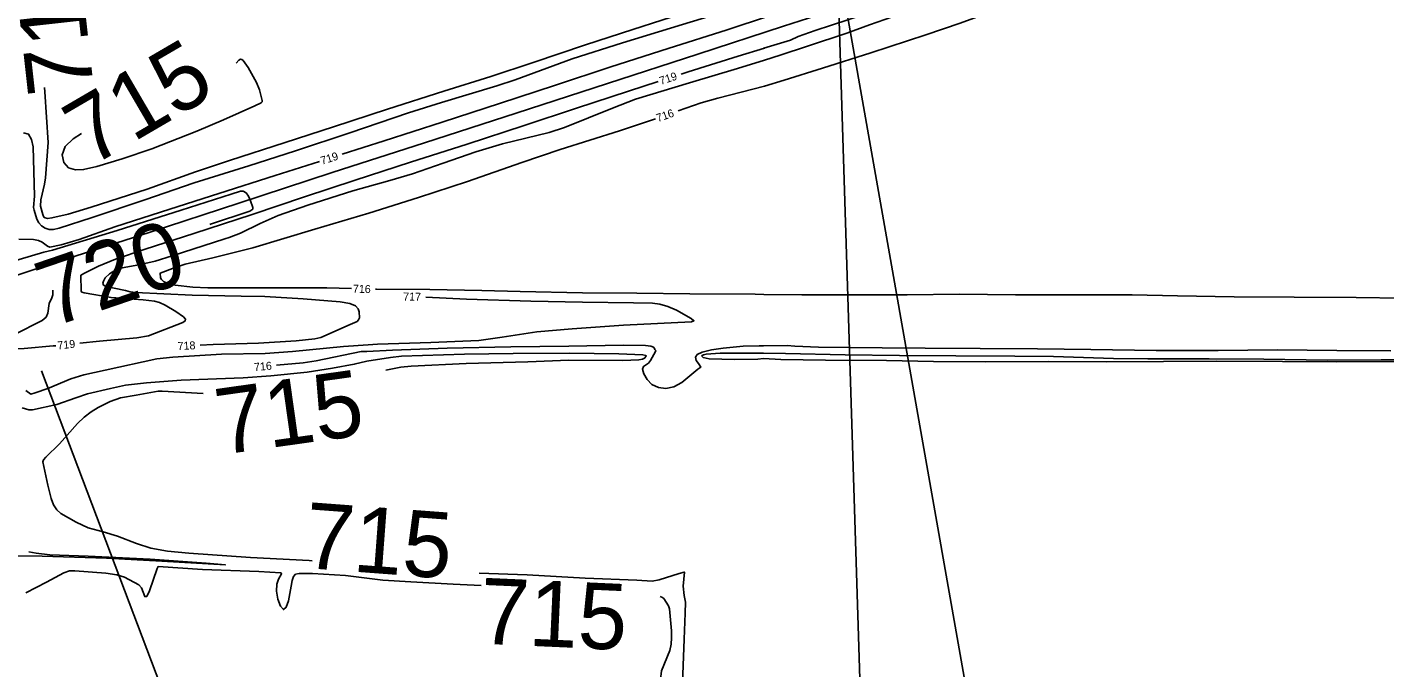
# Model space of a CAD drawing. Extents: x -468563856 to 36492962, y -306094093 to 11899197.
# Drawn here: x 1821764 to 1822443, y 530800 to 531121 of the extents above; entities that cross this region are included whole.
import ezdxf

# ---------------------------------------------------------------- set-up
doc = ezdxf.new("R2010")
doc.units = 0
for name, color, linetype in [('DT_X_Contour_Minor', 7, 'Continuous'), ('Level 14', 7, 'Continuous'), ('Level 19', 7, 'Continuous'), ('Level 40', 7, 'Continuous'), ('SH_Text', 7, 'Continuous')]:
    doc.layers.add(name, color=color, linetype=linetype)

msp = doc.modelspace()

# ---------------------------------------------------------------- linework, layer by layer
at = {"layer": 'DT_X_Contour_Minor'}
for points in [[(1822132.44, 531110.25), (1822145.7, 531114.41), (1822149.59, 531116.1), (1822157.97, 531119.11), (1822182.56, 531127.18), (1822210.23, 531136.13), (1822235.24, 531143.64), (1822260.34, 531151.8), (1822284.89, 531160.12), (1822311.53, 531168.93), (1822338.53, 531177.94), (1822366.96, 531187.21), (1822392.98, 531195.61), (1822415.55, 531202.84), (1822441.7, 531212.02), (1822457.43, 531217.42), (1822485.67, 531226.7), (1822513.96, 531235.56), (1822541.9, 531244.31), (1822572.45, 531253.71), (1822600.65, 531262.79), (1822628.9, 531272.08), (1822654.94, 531280.76), (1822671.39, 531286.17)], [(1822451.09, 531237.66), (1822425.97, 531229.73), (1822397.32, 531220.92), (1822371.29, 531212.64), (1822343.96, 531203.86), (1822312.87, 531193.61), (1822281.22, 531183.05), (1822251.62, 531173.44), (1822228.43, 531166.15), (1822200.9, 531157.19), (1822172.17, 531147.85), (1822146.73, 531139.54), (1822115.83, 531129.58), (1822091.67, 531122.23), (1822061.68, 531112.93), (1822036.58, 531104.94), (1822007.99, 531094.5), (1821998.97, 531091.41), (1821971.29, 531083.21), (1821954.8, 531077.96), (1821925.41, 531068.03), (1821898.18, 531059), (1821874.87, 531051.43), (1821847.61, 531042.99)], [(1822390.37, 531209.96), (1822374.4, 531204.87), (1822346.31, 531195.61), (1822319.96, 531186.97), (1822293.76, 531178.31), (1822267.78, 531169.88), (1822242.79, 531161.78), (1822215.73, 531152.9), (1822188.84, 531144.17), (1822163.48, 531135.96), (1822134.64, 531126.33), (1822114.03, 531119.54), (1822084.57, 531110.22), (1822055.85, 531101), (1822027.7, 531091.72), (1822000.77, 531082.85), (1821971.55, 531073.36), (1821942.62, 531064.04), (1821921.62, 531057.31)], [(1822462.06, 531210.89), (1822430.53, 531201.7), (1822402.62, 531192.71), (1822377.11, 531184.99), (1822350.02, 531176.7), (1822330.87, 531170.59), (1822305.34, 531162.02), (1822292.11, 531157.05), (1822275.26, 531150.3), (1822258.28, 531144.41), (1822244.67, 531140), (1822228.28, 531135.36), (1822209.84, 531130.07), (1822196.74, 531125.99), (1822185.22, 531121.96), (1822173.88, 531117.8), (1822154.26, 531111.38), (1822140.51, 531106.9), (1822132.67, 531104.27)], [(1822132.63, 531091.28), (1822142.54, 531094.32), (1822161.67, 531100.32), (1822185.92, 531108.05), (1822213.28, 531117), (1822230.57, 531122.82), (1822260.92, 531133.96), (1822287.86, 531143.13), (1822308.78, 531150.57), (1822317.45, 531153.55), (1822338.87, 531160.16), (1822364.37, 531167.87), (1822393.59, 531176.61), (1822417.02, 531183.69), (1822450.89, 531193.89)], [(1821772.8, 531090.67), (1821772.9, 531088.48), (1821774.65, 531063.14), (1821773.24, 531045.43), (1821772.74, 531042.31), (1821770.99, 531034.38), (1821770.86, 531031.33), (1821771.95, 531027.18), (1821772.52, 531025.85), (1821773.06, 531025.37), (1821774.22, 531025.17), (1821776.51, 531025.42), (1821784.6, 531027.33), (1821796.12, 531030.76), (1821824.03, 531039.86), (1821848.32, 531048.39), (1821865.31, 531054.13), (1821893.01, 531063.06), (1821917.23, 531070.96), (1821944.16, 531079.74), (1821972.41, 531088.87), (1821995.94, 531096.18), (1822017.08, 531103.1), (1822043.27, 531112.04), (1822066.95, 531119.71), (1822095.94, 531128.96)], [(1822090.98, 531097.33), (1822094.48, 531098.47), (1822119.54, 531106.3), (1822132.69, 531110.33)], [(1821868.51, 531102.86), (1821869.95, 531104.38), (1821870.78, 531104.78), (1821871.42, 531104.73), (1821872.13, 531104.14), (1821874.52, 531100.61), (1821878.8, 531093.11), (1821880.27, 531089.55), (1821881.61, 531084.22), (1821881.56, 531083.54), (1821881.13, 531083), (1821877.94, 531081.52), (1821862.25, 531074.53), (1821848.98, 531068.83), (1821826.36, 531060.01), (1821811.63, 531055.03), (1821798.87, 531051.05), (1821792.32, 531049.62), (1821788.34, 531049.45), (1821784.79, 531050.5), (1821782.38, 531053.21), (1821781.66, 531057.03), (1821783.17, 531061.19), (1821787.05, 531064.97), (1821791.26, 531067.61)], [(1822132.67, 531104.32), (1822119.18, 531100.1), (1822095.25, 531093.03), (1822068.18, 531084.78), (1822056.74, 531080.38), (1822032.78, 531070.72), (1822024.98, 531068.18), (1822001.8, 531062.47), (1821988.45, 531058.48), (1821972.04, 531052.8), (1821956.8, 531047.49), (1821945.4, 531044.1), (1821926.86, 531038.88), (1821904.49, 531031.78), (1821889.59, 531026.56), (1821880.6, 531022.61), (1821870.74, 531017.72), (1821865.08, 531015.63), (1821862.9, 531014.98), (1821836.58, 531006.39), (1821828.13, 531003.7), (1821819.92, 531001.99), (1821811.52, 531000.51), (1821807.91, 530999.12), (1821805.34, 530997.41), (1821803.18, 530995.5), (1821802.22, 530993.73), (1821801.96, 530992.73), (1821802.3, 530991.8), (1821803.53, 530991.12), (1821807.64, 530990.25), (1821813.26, 530989.15), (1821815.62, 530988.43), (1821818.3, 530988.11), (1821846.59, 530986.73), (1821871.08, 530986.33), (1821882.9, 530986.11), (1821902.15, 530984.85), (1821920.56, 530983.38), (1821925.35, 530982.55), (1821928.24, 530981.35), (1821929.58, 530979.89), (1821930.06, 530978.34), (1821930.2, 530975.49), (1821929.81, 530974.4), (1821929.03, 530973.63), (1821925.59, 530972.09), (1821910.96, 530965.6), (1821907.83, 530964.83), (1821898.53, 530963.89), (1821879.69, 530962.76), (1821857.05, 530962.07), (1821850.54, 530961.79)], [(1821790.41, 530962.74), (1821800.32, 530963.8), (1821818.88, 530965.42), (1821824.83, 530966.46), (1821841.91, 530973.04), (1821843.03, 530973.86), (1821843.19, 530974.77), (1821842.33, 530975.85), (1821838.36, 530978.58), (1821833.02, 530981.75), (1821830.3, 530983.01), (1821827.69, 530983.8), (1821822.08, 530984.46), (1821806.05, 530985.57), (1821792.59, 530987.92), (1821791.44, 530988.3), (1821791.08, 530988.82), (1821790.94, 530996.75), (1821793.18, 530998.01), (1821799.84, 531001.22), (1821808.3, 531004.72), (1821823.09, 531009.7), (1821847.51, 531017.65), (1821876.66, 531027.13), (1821902.71, 531035.89), (1821928.08, 531044.26), (1821955.68, 531053.23), (1821984.01, 531062.29), (1822012.57, 531071.62), (1822038.71, 531080.24), (1822064.76, 531088.75), (1822079.58, 531093.6)], [(1822132.63, 531091.28), (1822109.43, 531085.24), (1822101.08, 531082.92), (1822089.48, 531078.91)], [(1822078.13, 531075.01), (1822060.25, 531068.97), (1822030.53, 531059.55), (1822011.44, 531053.19), (1821984.17, 531043.64), (1821959.77, 531035.55), (1821934.88, 531027.85), (1821907.87, 531019.72), (1821876.99, 531010.38), (1821856.89, 531005.5), (1821843.05, 531002.24), (1821838.17, 531000.66), (1821830.54, 530997.71), (1821830.81, 530995.48), (1821831.2, 530994.52), (1821832.24, 530993.52), (1821834.47, 530992.58), (1821838.16, 530991.8), (1821847.01, 530990.78), (1821854.36, 530990.44), (1821883.1, 530990.46), (1821913.84, 530990.35), (1821926.29, 530990.04)], [(1821847.61, 531042.99), (1821822.99, 531034.51), (1821796.53, 531025.61), (1821780.17, 531020.28), (1821777.25, 531019.65), (1821775.03, 531019.65), (1821773.06, 531020.24), (1821771.32, 531021.36), (1821769.91, 531022.93), (1821768.91, 531024.82), (1821767.58, 531029.28), (1821767.29, 531030.68), (1821767.71, 531036.36), (1821767.03, 531060.97), (1821766.33, 531064.71), (1821764.82, 531067.31), (1821762.32, 531067.94)], [(1821910.19, 531053.65), (1821888.05, 531046.57), (1821859.97, 531037.56), (1821835.49, 531029.76), (1821807.9, 531020.91), (1821790.12, 531014.66), (1821781.05, 531011.97), (1821775.39, 531010.76), (1821774.32, 531011.25), (1821771.6, 531013.28), (1821769.81, 531014.05), (1821767.21, 531014.59), (1821759.94, 531014.74)], [(1821855.39, 531022.1), (1821855.71, 531022.2), (1821875.44, 531028.77), (1821876.91, 531029.8), (1821876.89, 531030.58), (1821875.77, 531034), (1821874.79, 531036.26), (1821873.55, 531038.01), (1821872.12, 531038.75), (1821870.69, 531038.73), (1821866.17, 531037.36), (1821841.15, 531029.34), (1821809.03, 531019.16), (1821776.83, 531009.26), (1821772.38, 531008.25), (1821749.21, 531001.46)], [(1821556.93, 530931.18), (1821556.34, 530929.44), (1821556.77, 530927.2), (1821557.46, 530926.02), (1821559.59, 530926.08), (1821574.45, 530930.55), (1821608.44, 530941.22), (1821633.7, 530949.47), (1821661.44, 530958.4), (1821673.02, 530961.83), (1821679.91, 530963.4), (1821684.7, 530963.89), (1821703.51, 530964.55), (1821729.33, 530965.12), (1821755.5, 530966.09), (1821757.73, 530967.01), (1821771.63, 530974.15), (1821773.55, 530975.78), (1821774.46, 530977.69), (1821775.14, 530982.55), (1821776.5, 530985.4), (1821777, 530986.98), (1821776.97, 530989.17), (1821776.97, 530989.24)], [(1821763.49, 530939.01), (1821765.91, 530937.15), (1821768.07, 530937.82), (1821774.46, 530940.09), (1821785.9, 530944.89), (1821792.49, 530946.83), (1821803.15, 530949.25), (1821828.86, 530954.87), (1821836.91, 530955.66), (1821861.32, 530957.22), (1821883.12, 530957.56), (1821896.76, 530958.56), (1821922.17, 530961.13), (1821934.55, 530961.97), (1821939.19, 530962.19), (1821965.95, 530963.12), (1821989.89, 530964), (1822001.61, 530965.76), (1822018.93, 530968.38), (1822036.52, 530969.93), (1822062.18, 530971.7), (1822096.17, 530973.38), (1822097.39, 530973.97), (1822095.97, 530975.12), (1822088.71, 530979.18), (1822084.35, 530981.05), (1822080.33, 530982.17), (1822076.75, 530982.67), (1822067.18, 530983), (1822041.71, 530983.33), (1822015.88, 530983.76), (1821983.68, 530984.7), (1821963.34, 530985.74)], [(1821938.29, 530989.74), (1821938.8, 530989.73), (1821965.48, 530989.6), (1821991.37, 530989.13), (1822010.54, 530988.63), (1822041.79, 530987.93), (1822068.83, 530987.76), (1822095.42, 530987.48), (1822127.98, 530987.18), (1822132.3, 530987.13)], [(1822132.3, 530987.13), (1822151.3, 530986.96), (1822175.24, 530986.9), (1822203.98, 530987), (1822230.23, 530987.19), (1822258.15, 530986.9), (1822288.59, 530986.93), (1822316.45, 530986.84), (1822339.17, 530986.48), (1822367.47, 530985.92), (1822397.44, 530985.77), (1822428.46, 530985.56), (1822451.89, 530985.22)], [(1821525.61, 530913.05), (1821536.33, 530916.51), (1821560.44, 530924.1), (1821589.51, 530933.21), (1821610.74, 530939.68), (1821641.28, 530948.87), (1821668.96, 530957.14), (1821687.52, 530960.17), (1821693.34, 530961.03), (1821700.64, 530961.39), (1821718.09, 530961.61), (1821735.5, 530962.14), (1821740.94, 530962.65), (1821742.65, 530963), (1821751.36, 530962.68), (1821753.21, 530962.09), (1821759.1, 530959.83), (1821762.67, 530960), (1821777.19, 530961.33), (1821778.48, 530961.47)], [(1821943.46, 530949.15), (1821950.93, 530950.78), (1821956.12, 530951.29), (1821983.48, 530952.5), (1822014.45, 530953.37), (1822034.89, 530954.3), (1822061.9, 530954.07), (1822069.84, 530954.36), (1822071.71, 530954.71), (1822072.76, 530955.2), (1822073.46, 530956.22), (1822073.33, 530956.6), (1822071.81, 530956.88), (1822059.85, 530957.37), (1822035.29, 530957.78), (1822007.07, 530957.65), (1821982.68, 530957.32), (1821951.18, 530956.22), (1821945.66, 530955.64), (1821933.96, 530953.74), (1821927.64, 530952.22), (1821916.72, 530950.23), (1821904, 530948.21), (1821885.85, 530946.36), (1821872.05, 530945.36), (1821841.03, 530944.31), (1821823.69, 530942.93), (1821813.21, 530941.69), (1821805.71, 530940.04), (1821794.23, 530937.31), (1821788.42, 530935.33), (1821778.86, 530932.03), (1821766.74, 530929.39), (1821764.98, 530929.42), (1821761.56, 530930.34)], [(1822132.22, 530961.39), (1822129.99, 530961.42), (1822122.09, 530961.24), (1822111.97, 530960.29), (1822106.16, 530959.4), (1822101.51, 530958.28), (1822099.03, 530956.99), (1822098.24, 530955.73), (1822098.49, 530954.09), (1822099.68, 530952.63), (1822100.88, 530950.74), (1822099.43, 530949.78), (1822091.3, 530943.12), (1822087.32, 530940.94), (1822083.34, 530940.06), (1822079.63, 530940.49), (1822076.43, 530942.08), (1822073.96, 530944.58), (1822072.37, 530947.35), (1822071.79, 530949.68), (1822072.26, 530951.08), (1822074.65, 530952.78), (1822075.68, 530954.11), (1822078.21, 530958.53), (1822078.36, 530959.01), (1822077.91, 530959.57), (1822077.77, 530960.1), (1822077.28, 530960.7), (1822075.92, 530961.22), (1822073.17, 530961.55), (1822062.09, 530961.67), (1822034.94, 530961.26), (1822005.81, 530960.9), (1821974.13, 530960.2), (1821946.71, 530959.21), (1821933.98, 530958.58), (1821931.08, 530958.58), (1821908.52, 530953.97), (1821902.05, 530952.91), (1821888.82, 530951.75)], [(1822132.2, 530954.99), (1822129.43, 530954.76), (1822117.66, 530954.63), (1822105.04, 530954.94), (1822102.08, 530955.51), (1822101.39, 530956.24), (1822101.52, 530956.62), (1822102.17, 530956.96), (1822103.54, 530957.26), (1822110.49, 530957.66), (1822132.21, 530957.82)], [(1822132.21, 530957.8), (1822143.14, 530957.62), (1822173.04, 530956.93), (1822200.11, 530956.65), (1822228.4, 530956.45), (1822257.79, 530956.32), (1822277.17, 530956), (1822307.13, 530955.06), (1822324.35, 530954.82), (1822354.93, 530954.86), (1822382.28, 530954.66), (1822413.97, 530954.26), (1822440.93, 530954.38), (1822457.82, 530954.48)], [(1822445.87, 530958.89), (1822418.82, 530959.15), (1822389.14, 530959.38), (1822359.48, 530959.09), (1822328.55, 530959.08), (1822295.87, 530959.49), (1822269.21, 530959.9), (1822240.44, 530960.12), (1822213.04, 530960.24), (1822191.52, 530960.43), (1822159.71, 530960.82), (1822147.92, 530961.25), (1822144.04, 530961.5), (1822132.22, 530961.43)], [(1822448.66, 530953.62), (1822418.67, 530953.48), (1822391.58, 530953.64), (1822358.42, 530953.7), (1822332.12, 530953.52), (1822303.65, 530953.47), (1822274.46, 530953.49), (1822243.28, 530953.45), (1822217.19, 530953.63), (1822193.76, 530954.02), (1822163.12, 530954.17), (1822140.8, 530954.52), (1822132.2, 530954.99)], [(1821906.66, 530853.89), (1821905.01, 530854.04), (1821875.83, 530855.5), (1821845, 530857.68), (1821834.26, 530858.74), (1821826, 530860.2), (1821818.73, 530862.51), (1821809.28, 530866.21), (1821802.17, 530868.27), (1821794.63, 530870.43), (1821788.56, 530873.27), (1821780.96, 530877.45), (1821778.92, 530879.35), (1821777.34, 530881.94), (1821776.14, 530885.06), (1821774.36, 530891.75), (1821771.91, 530903.3), (1821772.33, 530904.36), (1821773.36, 530905.69), (1821780.21, 530912.39), (1821789.22, 530922.61), (1821792.61, 530925.71), (1821796.11, 530928.36), (1821799.55, 530930.55), (1821805.55, 530933.5), (1821810.8, 530935.37), (1821818.64, 530936.8), (1821829.67, 530938.69), (1821831.53, 530938.77), (1821852.16, 530937.61)], [(1821764.96, 530858.4), (1821768.63, 530857.76), (1821775.5, 530856.91), (1821794.57, 530856.13), (1821825.58, 530854.66), (1821853.65, 530852.68), (1821863.24, 530851.81), (1821831.46, 530853.75), (1821803.82, 530855.11), (1821771.63, 530856.23), (1821744.83, 530856.35)], [(1821763.47, 530837.8), (1821773.77, 530843.23), (1821782.51, 530847.85), (1821785.34, 530848.78), (1821787.99, 530848.9), (1821803.4, 530847.61), (1821808.95, 530846.79), (1821812.72, 530845.67), (1821819.96, 530841.8), (1821821.22, 530840.28), (1821822.85, 530835.98), (1821823.85, 530835.97), (1821825.31, 530838.89), (1821829.04, 530849.95), (1821829.56, 530850.94), (1821851.68, 530849.54), (1821879.97, 530848.45), (1821890.95, 530847.8), (1821891.33, 530847.37), (1821889.77, 530844.68), (1821888.95, 530842.12), (1821888.72, 530838.69), (1821889.39, 530834.64), (1821890.68, 530831.09), (1821892.18, 530829.44), (1821893.56, 530830.6), (1821894.7, 530833.76), (1821896.1, 530841.2), (1821896.57, 530844.05), (1821897.21, 530846.07), (1821898.3, 530847.17), (1821900.09, 530847.57), (1821906.72, 530847.46), (1821923.2, 530846.56), (1821931.22, 530845.51), (1821941.94, 530844.18), (1821955.97, 530843.37), (1821977.06, 530842.24), (1821990.99, 530841.43)], [(1821958.88, 530849.51), (1821958.86, 530849.51)], [(1822093.74, 530662.91), (1822093.72, 530667.68), (1822092.94, 530687.66), (1822092.94, 530705.62), (1822093.44, 530730.52), (1822093.39, 530744.21), (1822092.86, 530756.67), (1822091.78, 530774.92), (1822091.61, 530788.25), (1822092.54, 530814.67), (1822093.12, 530827.67), (1822093.27, 530833.18), (1822092.53, 530836.49), (1822092.07, 530841.2), (1822092.67, 530848.2), (1822092.48, 530848.25), (1822089.97, 530847.57), (1822079.96, 530844.35), (1822076.48, 530843.73), (1822068.89, 530844.24), (1822043, 530845.11), (1822014.05, 530846.85), (1821990.08, 530847.71)], [(1822080.47, 530835.95), (1822081.38, 530835.64), (1822082.32, 530835.02), (1822084.78, 530831.35), (1822085.14, 530829.87), (1822086.16, 530818.85), (1822086.26, 530815.4), (1822086.04, 530812.13), (1822085.31, 530808.99), (1822081.28, 530798.83), (1822080.66, 530794.48), (1822080.52, 530789.64), (1822080.85, 530768.77), (1822080.43, 530743.97), (1822080.83, 530739.36), (1822083.44, 530720.8), (1822083.52, 530710.51), (1822083.16, 530697.98), (1822082.72, 530692.03), (1822080.65, 530674.88), (1822080.8, 530671), (1822081.86, 530663.1), (1822081.9, 530662.98)]]:
    msp.add_lwpolyline(points, dxfattribs=at)
at = {"layer": 'Level 14'}
msp.add_lwpolyline([(1822444.29, 531219.73), (1822402.07, 531205.86), (1822362.27, 531192.96), (1822315.04, 531177.42), (1822270.18, 531162.88), (1822228.03, 531149.28), (1822183.88, 531134.78), (1822142.19, 531121.34), (1822099.37, 531107.28), (1822054.26, 531092.67), (1822008.51, 531077.84), (1821962.66, 531063), (1821916.5, 531048.08), (1821870, 531032.72), (1821825.04, 531018.18), (1821780.22, 531003.71), (1821737.66, 530989.77), (1821648.73, 530960.74), (1821601.95, 530945.47), (1821553.57, 530929.66), (1821503.52, 530913.42), (1821454.26, 530897.29), (1821404.04, 530881.11)], dxfattribs=at)
at = {"layer": 'Level 40'}
msp.add_line((1821858.36, 530718.77), (1821771.32, 530948.98), dxfattribs=at)
at = {"layer": 'SH_Text'}
msp.add_lwpolyline([(1822184.44, 530662.05), (1822168.94, 531156.04), (1822252.12, 530684.02)], close=True, dxfattribs=at)

# ---------------------------------------------------------------- texts
at = {"layer": 'Level 19'}
for s, height, rotation, p in [('715', 33, 96.34285, (1821797.58, 531088.97)), ('715', 33, 30.27597, (1821795.82, 531050.66)), ('719', 4, 18.11693, (1822080.9, 531091.93)), ('716', 4, 19.07949, (1822079.4, 531073.31)), ('719', 4, 17.77315, (1821911.5, 531051.97)), ('720', 33, 18.91907, (1821776.17, 530970.44)), ('716', 4, 358.58564, (1821926.89, 530988.02)), ('717', 4, 358.77471, (1821952.04, 530984.1)), ('719', 4, 6.07908, (1821779.43, 530959.56)), ('718', 4, 2.49237, (1821839.39, 530959.3)), ('716', 4, 5.00192, (1821877.69, 530948.77)), ('715', 33, 8.02141, (1821860.82, 530906.81)), ('715', 33, 355.74949, (1821901.95, 530850.32)), ('715', 33, 357.45691, (1821989.86, 530812.44))]:
    msp.add_text(s, height=height, rotation=rotation, dxfattribs=at).set_placement(p)

doc.saveas('drawing.dxf')
